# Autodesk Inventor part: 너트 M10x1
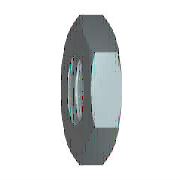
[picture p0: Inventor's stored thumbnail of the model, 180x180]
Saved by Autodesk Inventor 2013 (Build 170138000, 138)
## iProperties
Created: 2012-02
Part Number: 너트 M10x1
Material: 강철, 연강
Description: 6각 가는 너트 - 이중 모따기(부품 등급 A) - 정밀 나사산
Document SubType Name: Modeling
Standard: JIS B 1181
Designer: mduedu
Standards Organization: JIS
Language: ko-KR
Size Designation: M10x1
Categories: <MemberInstance><Categories><Category DisplayName="조임쇠" InternalName="e4da775c-781d-43d5-af7c-5136215cf5a6" Mnemonic="FSTN"><Category DisplayName="너트" InternalN
Density: 7.86 g/cm^3
Mass: 6.13139 g
Surface Area: 6.99154 cm^2
Volume: 0.780075 cm^3
IsCustomPart: 1
Author: mduedu
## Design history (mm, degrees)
node "MSC_A1"
node "MSC_PT1"
node "MSC_PT2"
node "MSC_PF1"
body "Solid1"
sketch "스케치1"
  geometry: L1 (8, 4.619)-(8, -4.619); L2 (8, -4.619)-(0, -9.238); L3 (0, -9.238)-(-8, -4.619); L4 (-8, -4.619)-(-8, 4.619); L5 (-8, 4.619)-(0, 9.238); L6 (0, 9.238)-(8, 4.619); C1 r 8 at (0, 0); 2 further points
  constraints: 12 end point, 2 coincident, 1 centre point, 1 tangent, 1 vertical, 11 other
  dimensions: "d0" = 16 diameter of C1 (= ParS)
extrude "돌출1" new body sketch "스케치1" distance "d1" = 5 (= M); taper "d2" = 0 deg
sketch "스케치2"
  geometry: L1 (-8, 4.619)-(0, 9.238) reference; L2 (0, -9.238)-(-8, -4.619) reference; L3 (-8, 4.619)-(8, -4.619); L4 (-8, -4.619)-(8, 4.619); 1 further point
  constraints: 4 end point, 2 midpoint, 2 parallel
hole "구멍1" sketch "스케치2" diameter "d3" = 8.91747; stored, may be unused: countersink angle "d7" = 90 deg, drill point angle "d9" = 118 deg; dims "d4" = 6, "d5" = 4, "d6" = 2, "d8" = 8
chamfer "모따기1" distance "d10" = 0.5 (= 0.5 x PTC); stored, may be unused: second distance "d11" = 2, angle "d12" = 45 deg
revolve "회전1" stored, may be unused: angle "d15" = 90 deg
sketch "스케치3"
  geometry: L1 (-9.238, 5)-(-9.238, 4.285); L2 (-9.238, 4.285)-(-8, 5); L3 (-8, 5)-(-9.238, 5); L4 (-9.238, 0.715)-(-9.238, 0); L5 (-9.238, 0)-(-8, 0); L6 (-8, 0)-(-9.238, 0.715); L7 (0, 6)-(0, -1) reference; L8 (-4.619, 5)-(-9.238, 5) reference; L9 (-4.619, 0)-(-9.238, 0) reference; L10 (-9.238, 0)-(-9.238, 5) reference
  constraints: 12 end point, 4 collinear, 3 perpendicular, 2 equal length, 1 vertical
  dimensions: "d13" = 30 deg angle of L2 L3; "d14" = 8 distance from line of L2.end L7 (= 0.5 x ParS)
other parameters: "ParS" = 16 [user parameter; used in 2 equation terms], "M" = 5 [user parameter; used in 1 equation term], "PTC" = 1 [user parameter; used in 1 equation term], "d17" = 0, "d18" = 0, "d19" = 0, "d20" = 0, "d21" = 0, "d22" = 0, "d23" = 0
